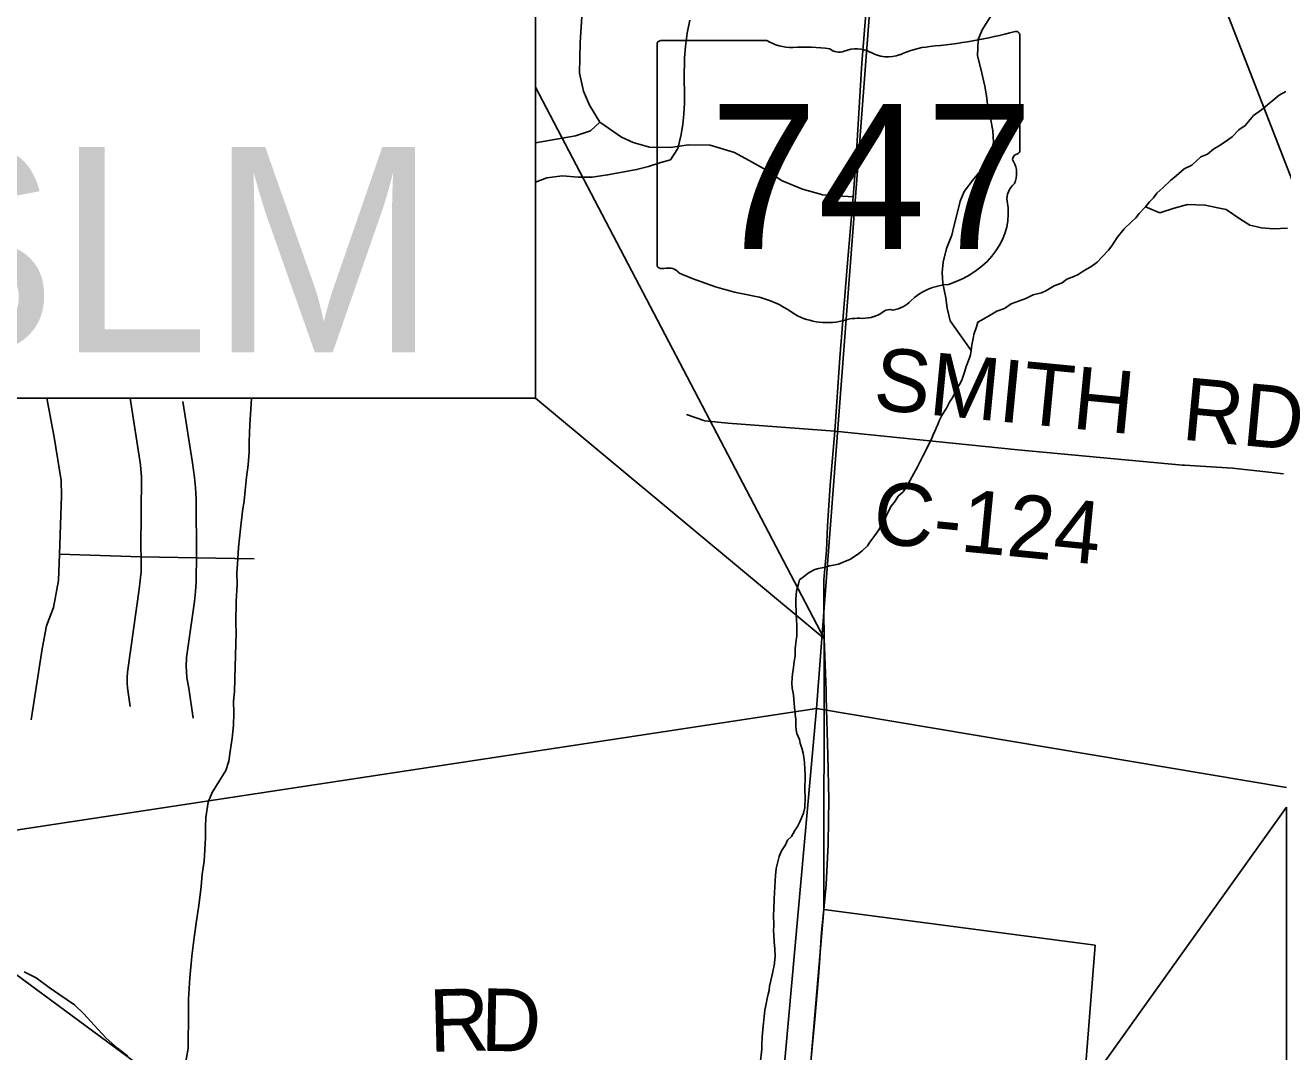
# Model space of a CAD drawing. Extents: x 0 to 34, y 0 to 22.
# Drawn here: x 3.964 to 5.107, y 18.207 to 19.14 of the extents above; entities that cross this region are included whole.
import ezdxf

# ---------------------------------------------------------------- set-up
doc = ezdxf.new("R2010")
doc.units = 0
for name, color, linetype in [('GM_X_County_Road', 7, 'Continuous'), ('GM_X_County_Road_Text', 7, 'Continuous'), ('GM_X_Minor_River', 7, 'Continuous'), ('GM_X_Rail_Line', 7, 'Continuous'), ('GM_X_Section', 7, 'Continuous'), ('GM_X_State_Route', 7, 'Continuous'), ('GM_X_State_Shield', 7, 'Continuous'), ('GM_X_Township_Road', 7, 'Continuous'), ('SH_Text', 7, 'Continuous')]:
    doc.layers.add(name, color=color, linetype=linetype)

msp = doc.modelspace()

# ---------------------------------------------------------------- linework, layer by layer
at = {"layer": 'GM_X_County_Road'}
for points in [[(5.161, 18.7471), (5.1674, 18.7519), (5.169, 18.7561), (5.1733, 18.8123), (5.1758, 18.8558), (5.1727, 18.8724), (5.1612, 18.8948), (5.1426, 18.9289), (5.0287, 19.2221), (5.0277, 19.238), (5.0278, 19.2591), (5.0324, 19.303), (5.0407, 19.4239), (5.0482, 19.4989)], [(4.6998, 18.771), (4.8661, 18.7543), (5.0157, 18.7403)], [(5.0157, 18.7403), (5.0176, 18.7401), (5.0611, 18.7376), (5.0943, 18.734), (5.1075, 18.7325)]]:
    msp.add_lwpolyline(points, dxfattribs=at)
at = {"layer": 'GM_X_Minor_River'}
for points in [[(4.4279, 18.9975), (4.4382, 19.0015), (4.4523, 19.0033), (4.4667, 19.0021), (4.4793, 19.0021), (4.4934, 19.004), (4.5083, 19.0069), (4.5197, 19.0089), (4.5305, 19.0116), (4.5416, 19.0154), (4.5504, 19.0178), (4.5572, 19.0279), (4.5602, 19.0407), (4.5616, 19.0502), (4.5627, 19.0593), (4.5633, 19.0691), (4.5632, 19.0782), (4.5628, 19.0912), (4.5634, 19.1105), (4.5641, 19.1208), (4.5656, 19.1329), (4.5682, 19.1446)], [(4.8236, 18.8445), (4.8046, 18.8713), (4.8019, 18.8828), (4.8006, 18.8923), (4.798, 18.9053), (4.7975, 18.9152), (4.7982, 18.9247), (4.8012, 18.9372), (4.8061, 18.9492), (4.8083, 18.9582), (4.8109, 18.9688), (4.8138, 18.9801), (4.8175, 18.9888), (4.8262, 19.0003), (4.8369, 19.0133), (4.8417, 19.0241), (4.8439, 19.0339), (4.8435, 19.0442), (4.8415, 19.0542), (4.8388, 19.0656), (4.8376, 19.0759), (4.8363, 19.0847), (4.8326, 19.1004), (4.8295, 19.1123), (4.83, 19.1271), (4.8336, 19.1357), (4.844, 19.1522)], [(4.7547, 18.7075), (4.7574, 18.712), (4.762, 18.7161), (4.7659, 18.7221), (4.7683, 18.7266), (4.7718, 18.7327), (4.775, 18.7387), (4.7777, 18.7443), (4.7797, 18.7485), (4.7832, 18.7549), (4.786, 18.7605), (4.7876, 18.7639), (4.7888, 18.7673), (4.7907, 18.7711), (4.7931, 18.7767), (4.7951, 18.7812), (4.7975, 18.7861), (4.8014, 18.7921), (4.8045, 18.7982), (4.8069, 18.8015), (4.81, 18.8083), (4.814, 18.8151), (4.8155, 18.8185), (4.8176, 18.8249), (4.8192, 18.8298), (4.822, 18.837), (4.8232, 18.8404), (4.8236, 18.8445), (4.8245, 18.8495), (4.8257, 18.8555), (4.8262, 18.8589), (4.8286, 18.8661), (4.8298, 18.8703), (4.8352, 18.8732), (4.8409, 18.8765), (4.847, 18.8802), (4.8539, 18.8827), (4.86, 18.8868), (4.8734, 18.8918), (4.8802, 18.8951), (4.8878, 18.8968), (4.8917, 18.8987), (4.8993, 18.9031), (4.9065, 18.906), (4.9108, 18.9093), (4.9169, 18.9118), (4.9211, 18.9136), (4.9245, 18.9158), (4.9287, 18.9184), (4.9326, 18.9206), (4.9383, 18.9247), (4.9426, 18.9292), (4.9484, 18.9355), (4.9515, 18.9396), (4.9538, 18.943), (4.9565, 18.9471), (4.9627, 18.955), (4.9697, 18.9617), (4.9735, 18.965), (4.9763, 18.9688), (4.9821, 18.9751), (4.9859, 18.9796), (4.9894, 18.9833), (4.9925, 18.9875), (4.9979, 18.9923), (5.0049, 18.999), (5.0099, 19.0031), (5.0172, 19.0094), (5.0244, 19.013), (5.0325, 19.0205), (5.0386, 19.023), (5.0444, 19.0278), (5.049, 19.0304), (5.0566, 19.0356), (5.0609, 19.0385), (5.067, 19.0449), (5.0728, 19.0489), (5.0802, 19.0579), (5.0875, 19.0631), (5.1036, 19.0764), (5.1097, 19.0797)], [(4.9821, 18.9751), (4.9952, 18.9696), (5.0083, 18.9738), (5.0202, 18.9772), (5.0365, 18.9764), (5.0463, 18.9745), (5.0554, 18.9727), (5.068, 18.964), (5.077, 18.9584), (5.0876, 18.9558), (5.0986, 18.9551), (5.1111, 18.9555)], [(4.1055, 18.1724), (4.1123, 18.2105), (4.1122, 18.2197), (4.1126, 18.2341), (4.1125, 18.255), (4.1138, 18.2744), (4.1156, 18.2941), (4.1176, 18.3111), (4.1199, 18.3262), (4.1219, 18.3402), (4.1239, 18.3573), (4.125, 18.3687), (4.1268, 18.3804), (4.1275, 18.3906), (4.1279, 18.402), (4.1281, 18.4115), (4.1284, 18.4202), (4.1303, 18.4339), (4.134, 18.4429), (4.1404, 18.453), (4.1464, 18.4627), (4.1493, 18.4713), (4.1503, 18.48), (4.1522, 18.4921), (4.1533, 18.5039), (4.1536, 18.5149), (4.1535, 18.5259), (4.1542, 18.5346), (4.1549, 18.5574), (4.1558, 18.5878), (4.1556, 18.5969), (4.1558, 18.6167), (4.1567, 18.6319), (4.1566, 18.6421), (4.1574, 18.655), (4.158, 18.6653), (4.1597, 18.6823), (4.1617, 18.6986), (4.1631, 18.7077), (4.1641, 18.7172), (4.1652, 18.7293), (4.1667, 18.7407), (4.1678, 18.7524), (4.1677, 18.7615), (4.1682, 18.7771), (4.1693, 18.7911), (4.1699, 18.801)], [(4.6319, 18.1963), (4.6334, 18.2095), (4.6334, 18.2141), (4.6339, 18.2202), (4.6345, 18.2278), (4.635, 18.2331), (4.6355, 18.2392), (4.6363, 18.2449), (4.6376, 18.2509), (4.6384, 18.2555), (4.6393, 18.2596), (4.6401, 18.263), (4.6406, 18.2668), (4.643, 18.277), (4.6439, 18.2816), (4.6447, 18.2854), (4.6457, 18.2937), (4.6454, 18.3006), (4.6448, 18.307), (4.6445, 18.3135), (4.6442, 18.3173), (4.6443, 18.3215), (4.6442, 18.3318), (4.6443, 18.3363), (4.6448, 18.3462), (4.6449, 18.3515), (4.6455, 18.3626), (4.646, 18.3675), (4.6465, 18.3736), (4.6478, 18.3785), (4.6494, 18.3845), (4.6514, 18.3898), (4.6549, 18.3951), (4.6569, 18.3996), (4.6604, 18.4029), (4.6635, 18.4082), (4.6658, 18.412), (4.6682, 18.4161), (4.6714, 18.424), (4.6726, 18.4293), (4.6728, 18.4384), (4.6726, 18.4449), (4.6728, 18.4582), (4.6726, 18.4639), (4.6723, 18.47), (4.6717, 18.475), (4.671, 18.4784), (4.6699, 18.483), (4.6685, 18.4876), (4.6678, 18.491), (4.6653, 18.4964), (4.6646, 18.4998), (4.6643, 18.5033), (4.6644, 18.5094), (4.6637, 18.5136), (4.6628, 18.5238), (4.6622, 18.5315), (4.6612, 18.5376), (4.6609, 18.5425), (4.661, 18.5467), (4.6615, 18.5505), (4.6619, 18.5539), (4.6628, 18.5619), (4.6637, 18.5668), (4.6638, 18.5733), (4.6648, 18.5812), (4.6652, 18.585), (4.6654, 18.5953), (4.6651, 18.5995), (4.6648, 18.6044), (4.6646, 18.609), (4.6643, 18.6124), (4.6644, 18.6189), (4.6649, 18.6257), (4.6669, 18.6325), (4.6678, 18.6359), (4.6766, 18.6426), (4.6816, 18.6455), (4.685, 18.6462), (4.6899, 18.6473), (4.6949, 18.6487), (4.6987, 18.6494), (4.7032, 18.6504), (4.7097, 18.6529), (4.7135, 18.6544), (4.7204, 18.6592), (4.7246, 18.6625), (4.7296, 18.667), (4.7316, 18.6704), (4.7363, 18.6763), (4.7398, 18.6816), (4.7425, 18.6865), (4.7461, 18.6929), (4.7476, 18.6967), (4.7512, 18.703), (4.7547, 18.7075)], [(4.0574, 18.2031), (4.0481, 18.2106), (4.0377, 18.2197), (4.0267, 18.2314), (4.0175, 18.2416), (4.009, 18.2498), (3.9956, 18.259), (3.9859, 18.2657), (3.974, 18.2744), (3.9631, 18.2797)]]:
    msp.add_lwpolyline(points, dxfattribs=at)
at = {"layer": 'GM_X_Rail_Line'}
msp.add_lwpolyline([(4.3528, 17.9844), (3.8782, 18.3346), (3.7815, 18.4067), (3.5682, 18.5641), (3.3277, 18.7422), (3.2626, 18.7894), (3.2446, 18.801)], dxfattribs=at)
at = {"layer": 'GM_X_Section'}
for points in [[(3.7253, 19.3633), (3.7257, 19.3674), (4.7613, 19.5448), (4.6831, 18.5192), (3.6423, 18.3609), (3.6787, 18.801)], [(5.1102, 18.4472), (4.6831, 18.5192), (4.7613, 19.5448), (5.7435, 19.3869), (5.6931, 18.7255)], [(5.6474, 18.1592), (5.5736, 17.336), (4.5906, 17.4897), (4.6831, 18.5192), (5.1102, 18.4472)]]:
    msp.add_lwpolyline(points, dxfattribs=at)
msp.add_lwpolyline([(4.6831, 18.5192), (4.5906, 17.4897), (3.5572, 17.3639), (3.6423, 18.3609)], close=True, dxfattribs=at)
at = {"layer": 'GM_X_State_Route'}
for points in [[(4.7164, 18.9842), (4.7189, 19.0149), (4.7243, 19.1056), (4.7319, 19.1993), (4.7401, 19.2864), (4.7442, 19.3363)], [(4.6921, 18.5293), (4.6919, 18.5351), (4.6901, 18.5827), (4.6898, 18.6075), (4.6899, 18.6361), (4.6922, 18.6626), (4.6933, 18.6851), (4.6957, 18.7221), (4.6998, 18.771), (4.7044, 18.8379), (4.7111, 18.9205), (4.7164, 18.9842)], [(4.6849, 18.2753), (4.6856, 18.2834), (4.6878, 18.316), (4.69, 18.3364), (4.6921, 18.3591), (4.6937, 18.3958), (4.6942, 18.4177), (4.6943, 18.4362), (4.6936, 18.4768), (4.6921, 18.5293)], [(4.6479, 17.823), (4.6523, 17.8636), (4.6547, 17.8932), (4.6627, 18.002), (4.6698, 18.083), (4.6732, 18.1415), (4.6746, 18.1631), (4.6817, 18.2366), (4.6849, 18.2753)]]:
    msp.add_lwpolyline(points, dxfattribs=at)
at = {"layer": 'GM_X_State_Shield'}
for p, q in [((4.5384, 19.1226), (4.5384, 18.9225)), ((4.6381, 19.126), (4.5416, 19.126)), ((4.8679, 19.0263), (4.8679, 19.131)), ((4.8679, 19.0263), (4.8679, 19.0263))]:
    msp.add_line(p, q, dxfattribs=at)
for centre, major_axis, start_param, end_param in [((4.7505, 19.3989), (0.3495, 0), 4.814394, 5.042369), ((4.8643, 19.1314), (0.00367, 0), 6.141152, 7.989035), ((4.5421, 19.123), (0.00382, 0), 1.712693, 3.28349), ((4.6611, 19.1493), (0.037, 0), 4.042523, 4.731795), ((4.6734, 19.0137), (0.133, 0), 1.404758, 1.657858), ((4.7951, 19.0649), (0.0703, 0), 1.699011, 2.107814), ((4.7036, 19.1241), (0.0107, 0), 3.836095, 5.185415), ((4.7193, 19.1009), (0.0222, 0), 0.950623, 2.079405), ((4.7479, 19.1327), (0.0267, 0), 4.081561, 5.145723), ((4.8671, 19.0186), (0.00568, 0), 1.883978, 3.671073), ((4.864, 19.0259), (0.00393, 0), 5.05454, 6.418171), ((4.831, 19.0054), (0.0341, 0), 5.934695, 6.695948), ((4.8811, 18.9825), (0.0248, 0), 2.387724, 3.262537), ((4.7701, 18.9692), (0.0874, 0), 5.101752, 6.440018), ((4.5422, 18.922), (0.00385, 0), 3.00124, 4.508301), ((4.5428, 18.9425), (0.0294, 0), 4.665946, 4.897461), ((4.5488, 18.9109), (0.0106, 0), 0.519207, 1.627899), ((4.6826, 19.0907), (0.2524, 0), 4.195997, 4.488961), ((4.807, 18.8663), (0.0479, 0), 1.647645, 2.488434), ((4.6073, 18.8326), (0.079, 0), 0.823519, 1.323587), ((4.7495, 18.8756), (0.00752, 0), 1.147584, 2.315152), ((4.7463, 18.9031), (0.0282, 0), 4.937069, 5.64225), ((4.6928, 18.9099), (0.0501, 0), 4.026481, 4.996735), ((4.7217, 18.8408), (0.0412, 0), 1.495662, 1.94098), ((4.7254, 18.895), (0.0267, 0), 4.691044, 5.507374)]:
    msp.add_ellipse(centre, major_axis=major_axis, ratio=0.8, start_param=start_param, end_param=end_param, dxfattribs=at)
at = {"layer": 'GM_X_Township_Road'}
for p in [(4.69, 18.3364), (4.9233, 18.1379)]:
    msp.add_line(p, (4.9365, 18.304), dxfattribs=at)
for points in [[(4.6247, 19.0156), (4.6087, 19.0245), (4.5865, 19.0311), (4.5668, 19.0314), (4.5505, 19.0288), (4.5314, 19.0293), (4.5166, 19.0335), (4.5059, 19.0384), (4.4862, 19.0518), (4.4769, 19.0675), (4.4716, 19.08), (4.4678, 19.0965), (4.4683, 19.1242), (4.472, 19.1807)], [(4.4862, 19.0518), (4.4778, 19.0442), (4.4643, 19.0395), (4.4279, 19.0332)], [(4.6416, 19.0055), (4.6349, 19.0099), (4.6247, 19.0156)], [(4.6869, 18.9866), (4.6706, 18.9912), (4.6515, 18.999), (4.6416, 19.0055)], [(4.7164, 18.9842), (4.6888, 18.986), (4.6869, 18.9866)], [(3.9696, 18.5088), (3.9797, 18.5732), (3.9835, 18.5944), (3.99, 18.6108), (3.9945, 18.6355), (3.9953, 18.6595), (3.9972, 18.7124), (3.9967, 18.7262), (3.9906, 18.7656), (3.9837, 18.801)], [(4.0595, 18.521), (4.0572, 18.5378), (4.0567, 18.5422), (4.0567, 18.5471), (4.057, 18.5521), (4.0574, 18.5543), (4.0678, 18.6276), (4.0694, 18.6433), (4.0696, 18.6537), (4.0695, 18.657), (4.0693, 18.6649), (4.0698, 18.7293), (4.069, 18.7407), (4.0594, 18.801)], [(4.1167, 18.5103), (4.1129, 18.5375), (4.111, 18.5471), (4.1106, 18.5534), (4.1104, 18.5573), (4.1107, 18.5655), (4.1179, 18.6165), (4.1188, 18.6254), (4.1194, 18.6342), (4.1196, 18.6379), (4.1197, 18.656), (4.1197, 18.6567), (4.1195, 18.7093), (4.1192, 18.7144), (4.119, 18.7201), (4.1181, 18.7291), (4.1162, 18.7425), (4.1074, 18.798)], [(4.6998, 18.771), (4.6026, 18.7783), (4.5818, 18.7805), (4.565, 18.7864)], [(3.9953, 18.6595), (4.0695, 18.657), (4.1197, 18.656), (4.1722, 18.6551)]]:
    msp.add_lwpolyline(points, dxfattribs=at)
at = {"layer": 'SH_Text'}
for points in [[(4.4279, 19.3633), (2.1739, 19.3633), (2.1739, 18.801), (4.4279, 18.801)], [(4.4279, 19.0838), (4.6901, 18.5827), (4.4279, 18.801)], [(5.1102, 18.4296), (4.6405, 17.7717), (5.1102, 18.1632)]]:
    msp.add_lwpolyline(points, close=True, dxfattribs=at)
msp.add_lwpolyline([(4.4077, 15.4283), (4.5869, 17.4825), (4.6405, 17.7714), (4.6732, 18.1415), (4.69, 18.3364), (4.6901, 18.5827)], dxfattribs=at)

# ---------------------------------------------------------------- texts
at = {"layer": 'GM_X_County_Road_Text'}
for s, height, rotation, p in [('SMITH', 0.05682, 354.4655, (4.7338, 18.7912)), ('RD', 0.05682, 354.6307, (5.0141, 18.7636)), ('C-124', 0.05682, 354.4812, (4.733, 18.6698)), ('R', 0.0568, 1.4228, (4.3317, 18.207)), ('D', 0.0568, 358.8032, (4.3777, 18.2082))]:
    msp.add_text(s, height=height, rotation=rotation, dxfattribs=at).set_placement(p)
at = {"layer": 'GM_X_State_Shield'}
msp.add_text('747', height=0.13184, dxfattribs=at).set_placement((4.5862, 18.9366))
at = {"layer": 'SH_Text'}
msp.add_text('BUT-747 3.12 SLM', height=0.18634, dxfattribs=at).set_placement((2.206, 18.8429))

doc.saveas('drawing.dxf')
